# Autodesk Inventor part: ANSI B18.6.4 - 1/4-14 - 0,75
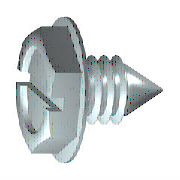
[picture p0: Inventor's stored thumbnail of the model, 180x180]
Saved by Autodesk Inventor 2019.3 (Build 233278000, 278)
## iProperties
Created: 2018-01
Part Number: ANSI B18.6.4 - 1/4-14 - 0,75
Material: Ocel, měkká
Description: Šroub do plechu s vroubkovanou šestihrannou hlavou s drážkou a podložkou - Typ BP - Palcový
Document SubType Name: Modeling
Standard: ANSI B18.6.4
Designer: B-hon
Standard Revision: 1998
Standards Organization: ANSI
Language: cs-CZ
Size Designation: 1/4-14 - 0,75
Categories: <MemberInstance><Categories><Category DisplayName="Spojovací materiál" InternalName="e4da775c-781d-43d5-af7c-5136215cf5a6" Mnemonic="FSTN"><Category DisplayName
Density: 7.85 g/cm^3
Appearance: Pololeštěná
IsCustomPart: 0
Author: B-hon
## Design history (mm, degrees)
sketch "Náčrt1"
  geometry: L1 (-1.27, 6.604)-(-1.27, 0); L2 (-1.27, 0)-(19.05, 0); L3 (19.05, 0)-(19.05, 3.175); L4 (19.05, 3.175)-(0, 3.175); L5 (0, 3.175)-(0, 6.604); L6 (-5.334, 0)-(23.114, 0) reference; L7 (0, -1.321)-(0, 7.925) reference; L8 (0, 6.604)-(-1.27, 6.604)
  constraints: 12 end point, 4 perpendicular, 2 collinear, 1 point on line, 1 vertical
  dimensions: "d0" = 1.27 distance between parallel lines of L1 L5 (= SD); "d1" = 6.35 diameter of L4 L2 (= NND); "d2" = 19.05 distance between parallel lines of L3 L5 (= NLG); "d18" = 13.208 diameter of L8 L2 (= SD2)
revolve "Těleso" sketch "Náčrt1" stored, may be unused: angle "d77" = 90 deg
sketch "Náčrt2"
  geometry: L1 (0, 5.499)-(4.763, 2.75); L2 (4.763, 2.75)-(4.762, -2.75); L3 (4.762, -2.75)-(0, -5.499); L4 (0, -5.499)-(-4.762, -2.75); L5 (-4.762, -2.75)-(-4.762, 2.75); L6 (-4.762, 2.75)-(0, 5.499); C1 r 6.604 at (0, 0) reference; 1 further point
  constraints: 12 end point, 1 coincident, 1 vertical, 11 other
  dimensions: "d7" = 9.525 distance between parallel lines of L2 L5 (= SW)
extrude "Hlava" join sketch "Náčrt2" distance "d9" = 4.826 (= KOH); taper "d10" = 0 deg
node "IDS_WORKPLANE{1}"
sketch "Náčrt3"
  geometry: C1 r 3.81 at (0, 0); 1 further point
  constraints: 1 centre point, 1 coincident
  dimensions: "d12" = 7.62 diameter of C1 (= SD3)
extrude "Zářez" cut sketch "Náčrt3" distance "d13" = 0.4826 (= SB); taper "d14" = 0 deg
sketch "Náčrt4"
  geometry: L1 (-6.096, 4.763)-(-6.096, 5.499); L2 (-6.096, 5.499)-(-5.509, 5.499); L3 (-6.096, 5.499)-(-6.096, 2.75) reference; L4 (-7.456, 0)-(1.988, 0) reference; L5 (-1.27, 5.499)-(-6.096, 5.499) reference; A1 r 8.249 centre (0.639, 0) between (-5.509, 5.499) and (-6.096, 4.763)
  constraints: 4 end point, 2 collinear, 2 point on circle, 2 point on line, 1 centre point, 1 perpendicular, 1 vertical
  dimensions: "d17" = 9.525 diameter of L1.start L4 (= SW); "d19" = 8.24889 radius of A1 (= 0.866025 x SW)
revolve "Zkosení1" sketch "Náčrt4" stored, may be unused: angle "d92" = 90 deg
sketch "Náčrt5"
  geometry: L1 (4.763, 2.75)-(4.762, -2.75) reference; L2 (-4.762, -2.75)-(-4.762, 2.75) reference; L3 (-9.246, 0)-(9.246, 0) reference; L4 (0, -9.246)-(0, 9.246) reference; L5 (-4.762, 0.953)-(4.763, 0.953); L6 (4.763, 0.953)-(4.763, -0.952); L7 (4.763, -0.952)-(-4.762, -0.952); L8 (-4.762, -0.952)-(-4.762, 0.953); L9 (-4.762, 0)-(4.763, 0)
  constraints: 10 end point, 3 collinear, 2 midpoint, 2 parallel, 1 horizontal, 1 perpendicular
  dimensions: "d20" = 1.905 distance of L5.end L6.end (= SBR)
extrude "Drážka" cut sketch "Náčrt5" distance "d21" = 2.5654 (= STI); taper "d22" = 0 deg
workplane "Work Plane3"
body "Solid1"
feature "Závit" dims "d3" = 19.05 (= GEL), "d4" = 0
chamfer "Zkosení2" distance "d15" = 3.175 (= -0.5 x GD2 + 0.5 x NND); stored, may be unused: second distance "d16" = 8.72319 (= SPTZ), angle "d101" = 45 deg
other parameters: "NLG" = 19.05 [user parameter; used in 1 equation term], "NND" = 6.35 [user parameter; used in 2 equation terms], "KOH" = 4.826 [user parameter; used in 2 equation terms], "GEL" = 19.05 [user parameter; used in 1 equation term], "SW" = 9.525 [user parameter; used in 4 equation terms], "GD2" = 0 [user parameter; used in 1 equation term], "SPTZ" = 8.72319 [user parameter; used in 1 equation term], "SD3" = 7.62 (= 0.8 x SW) [user parameter; used in 1 equation term], "SB" = 0.4826 (= 0.1 x KOH) [user parameter; used in 1 equation term], "d6" = 0, "d11" = 0, "SD2" = 13.208 [user parameter; used in 1 equation term], "SD" = 1.27 [user parameter; used in 1 equation term], "SBR" = 1.905 [user parameter; used in 1 equation term], "STI" = 2.5654 [user parameter; used in 1 equation term], "d102" = 0, "d103" = 0, "GD1" = 4.8768 [user parameter], "THREADDIA" = 6.35 [user parameter], "TOA" = 4.81362 [user parameter], "PTC" = 1.81429 (computed from TPU) [user parameter], "E0" = 10.99852 [user parameter]
